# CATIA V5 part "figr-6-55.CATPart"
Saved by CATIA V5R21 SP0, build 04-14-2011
Part number: Part1
Bounding box of the stored display mesh (mm): x -50.648 to 69.574, y -72.183 to 91.11, z 0 to 52
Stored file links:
  D:\CATIA V5R21 E-RESOURCES\CATIA-V5R21\catia-v5r21-prt\c06-catia-v5r21-prt\c06-catia-v5r21-figr-6-55.CATPart
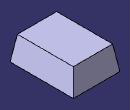
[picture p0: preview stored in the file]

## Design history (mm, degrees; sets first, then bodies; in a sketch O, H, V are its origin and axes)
Body1 (main body)
  Sketch1 on xy-plane, origin (0, 0, 0), H (1, 0, 0), V (0, 1, 0)
    line L1 (-50.6478, 72.1832) -> (50.6478, 72.1832)
    line L2 (50.6478, 72.1832) -> (50.6478, -72.1832)
    line L3 (50.6478, -72.1832) -> (-50.6478, -72.1832)
    line L4 (-50.6478, -72.1832) -> (-50.6478, 72.1832)
    axis line L5 (50.6478, -72.1832) -> (-50.6478, 72.1832)
    horizontal: L1 H, L3 H
    vertical: L2 V, L4 V
    midpoint: O L5
  Pad1: profile Sketch1, direction (0, 0, 1), length 52
  Draft1: Angle 20, Neutral face of Pad1, PullDir edge [face of Pad1 | face of Pad1], SupportToDraft (face of Pad1; face of Pad1)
